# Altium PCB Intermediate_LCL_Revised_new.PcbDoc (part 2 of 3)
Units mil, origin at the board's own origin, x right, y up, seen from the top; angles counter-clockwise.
Board outline 12850 x 6950 mil, 4 copper layers (Top Layer, Lay1, gnd, Bottom Layer), stack 23.756 mil thick; 473 components, 243 nets, 1278 pads, 73 vias.
Unrouted connection lines stored in the file: 289.
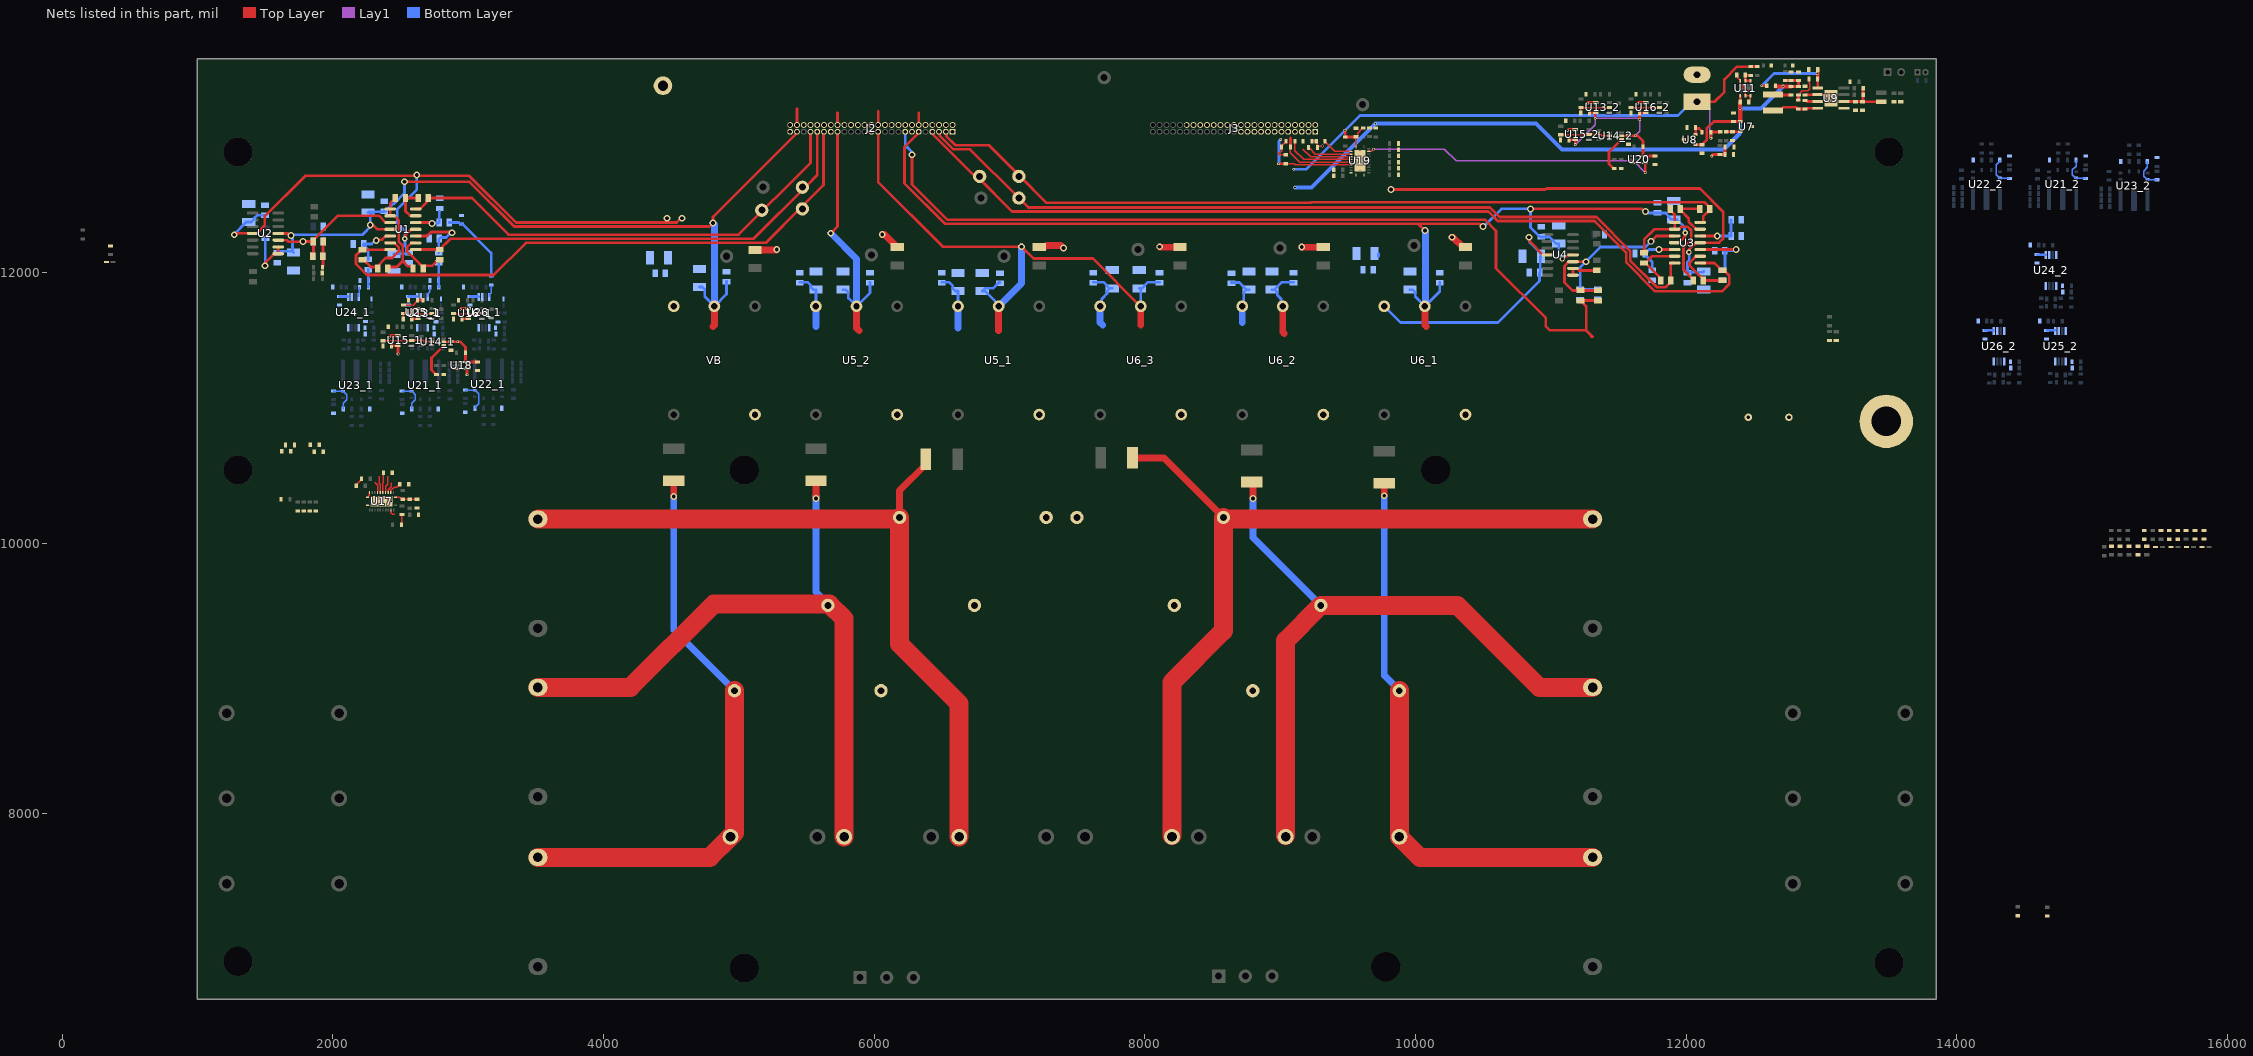
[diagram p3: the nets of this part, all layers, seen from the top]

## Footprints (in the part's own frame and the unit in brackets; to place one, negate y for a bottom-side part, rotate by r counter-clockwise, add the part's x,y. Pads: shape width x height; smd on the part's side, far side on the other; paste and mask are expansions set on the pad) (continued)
SHF-125-01-L-D-RA [mm] "50-Pin Simplus Connector"
  rect 1.09x1.09 hole 0.74 mask+0.381: 01(-15.24,-0.508)
  round 1.09 hole 0.74 mask+0.381: 02(-15.24,0.762) 03(-13.97,-0.508) 04(-13.97,0.762) 05(-12.7,-0.508) 06(-12.7,0.762) 07(-11.43,-0.508) 08(-11.43,0.762) 09(-10.16,-0.508) 10(-10.16,0.762) 11(-8.89,-0.508) 12(-8.89,0.762) 13(-7.62,-0.508) 14(-7.62,0.762) 15(-6.35,-0.508) 16(-6.35,0.762) 17(-5.08,-0.508) 18(-5.08,0.762) 19(-3.81,-0.508) 20(-3.81,0.762) 21(-2.54,-0.508) 22(-2.54,0.762) 23(-1.27,-0.508) 24(-1.27,0.762) 25(0,-0.508) 26(0,0.762) 27(1.27,-0.508) 28(1.27,0.762) 29(2.54,-0.508) 30(2.54,0.762) 31(3.81,-0.508) 32(3.81,0.762) 33(5.08,-0.508) 34(5.08,0.762) 35(6.35,-0.508) 36(6.35,0.762) 37(7.62,-0.508) 38(7.62,0.762) 39(8.89,-0.508) 40(8.89,0.762) 41(10.16,-0.508) 42(10.16,0.762) 43(11.43,-0.508) 44(11.43,0.762) 45(12.7,-0.508) 46(12.7,0.762) 47(13.97,-0.508) 48(13.97,0.762) 49(15.24,-0.508) 50(15.24,0.762)
  silkscreen extent -19.8,-0.61 19.05,7.36, body extent -19.05,-0.71 19.05,7.37, height 5.59
SOD-523_L1.2-W0.8-LS1.6-RD [mm]
  rect 0.93x0.36 smd: 1(-0.635,0) 2(0.635,0)
  silkscreen extent -0.91,-0.55 0.68,0.55
SOIC-14 [mm]
  oval 2.2x0.6 smd: 1(-2.4,3.81) 2(-2.4,2.54) 3(-2.4,1.27) 4(-2.4,0) 5(-2.4,-1.27) 6(-2.4,-2.54) 7(-2.4,-3.81) 8(2.4,-3.81) 9(2.4,-2.54) 10(2.4,-1.27) 11(2.4,0) 12(2.4,1.27) 13(2.4,2.54) 14(2.4,3.81)
  silkscreen extent -2.52,-4.4 0.9,4.78, body extent -2,-4.38 2,4.38, height 1.75
SOT-23-5_L3.0-W1.7-P0.95-LS2.8-BR [mm]
  rect 1x0.6 smd: 1(1.3,-0.95) 2(1.3,0) 3(1.3,0.95) 4(-1.3,0.95) 5(-1.3,-0.95)
  silkscreen extent -0.9,-1.78 1.65,1.55
VISH-TLMX1100_V [mm] "SMD, 2-Leads, Body 1.6x0.8mm"
  rect 0.6x0.8 smd: 1(-0.725,0) 2(0.725,0)
  silkscreen extent 1.53,-0.4 1.53,0.4, body extent -0.8,-0.4 0.8,0.4, height 0.65

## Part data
C1 C6 C11 C16: library part C2012X5R1H225K125AB, "SMD Multilayer Ceramic Capacitor, 2.2 µF, 50 V, 0805 [2012 Metric], ± 10%, X5R, C"
C2 C4 C7 C9 C12 C14 C17 C19 C23_1 C23_2 C23_3 C25_1 C25_2 C25_3 C28_1 C28_2 C28_3 C30_1 C30_2 C30_3: library part C0805C104J5RACTU, "SMD Multilayer Ceramic Capacitor, 0.1 µF, 50 V, 0805 [2012 Metric], ± 5%, X7R, C Series KEMET"
C3 C5 C8 C10 C13 C15 C18 C20 C24_1 C24_2 C24_3 C26_1 C26_2 C26_3 C29_1 C29_2 C29_3 C31_1 C31_2 C31_3: library part C3216X7R1H475K160AC, "SMD Multilayer Ceramic Capacitor, 4.7 µF, 50 V, 1206 [3216 Metric], ± 10%, X7R, C", Package=None
C21: library part 102_Y, "Y Earth Capacitor", Package=None
C22_1 C22_2 C22_3 C27_1 C27_2 C27_3: library part PHE450HF7220JR06L2, "KEMET PHE450 Metallised Polypropylene Film Capacitor, 180 V ac, 250 V dc, ±5%, 2.2μF, Through Hole", Manufacturer_Name=KEMET
C32 C33 C34 C35 C36 C37 C38 C39 C40 C41 C42 C43 C44 C45 C46 C47 C48 C50 C51 C54 C55_1 C55_2 C56_1 C56_2 C57_1 C57_2 C58_1 C58_2 C59_1 C59_2 C60_1 C60_2 C61_1 C61_2 C62 C63 C64 C65 C66 C67 C68 C69 C70 C71 C72 C73 C74 C75 C76 C77 C78 C79 C80 C81 C82 C83 C84_1 C84_2 C85_1 C85_2 C86_1 C86_2 C87_1 C87_2 C88_1 C88_2 C89_1 C89_2 C90_1 C90_2 C91_1 C91_2 C92_1 C92_2 C93_1 C93_2 C94_1 C94_2 C95_1 C95_2 C96_1 C96_2 C97_1 C97_2 C98_1 C98_2 C99_1 C99_2 C100_1 C100_2 C101_1 C101_2 C102_1 C102_2 C103_1 C103_2 C104_1 C104_2 C105_1 C105_2 C106_1 C106_2 C107_1 C107_2 C108_1 C108_2 C109_1 C109_2 C110_1 C110_2 C111_1 C111_2 C112_1 C112_2 C113_1 C113_2 C114_1 C114_2 C115_1 C115_2 C116_1 C116_2 C117_1 C117_2 C118_1 C118_2 C119_1 C119_2: library part Cap, "Capacitor"
C53: library part CE, "直插电解电容"
D1 D2 D3 D4 D5 D6 D7 D8: Average Rectified Current (Io)=70mA, Forward Voltage (Vf@If)=1V@15mA, JLCPCB Part Class="Extended Part", LCSC Part Name="电压:70V 电流:70mA", Manufacturer=Nexperia(安世), Reverse Leakage Current (Ir)=10uA@70V, Reverse Voltage (Vr)=70V
DS1 DS2: library part CMP-1666-00027-1_1, "LED, RED, 2.1 V, -40 to 100 degC, 2-Pin SMD (0603), RoHS, Tape and Reel", Capacitance="12 pF", Case Code (Imperial)=0603, Case Code (Metric)=1608, Max Operating Temperature=125degC, Min Operating Temperature=-55degC, Package Quantity=4000, Resistance="100000000000 Ohm", Tolerance=5%, Type (Capacitors)=C0G, Voltage Rating="50 V"
J2 J3: library part SHF-125-01-L-D-RA, "50-Pin Simplus Connector", Package=None
J4 J7: library part 3PinTerminal, "3 Position Terminal Block 5.08mm", Digikey Part Number=ED2610-ND, Manufacturer="On Shore Technology", Package=HDR03, Part Number=OSTTC032162, Temperature="-30°C to +105°C", Temperature Range High=+105°C, Temperature Range Low=-30°C, Voltage=300V
L1 L2: library part "30mH Custom CM Choke", "30mH Custom CM Choke", Manufacturer_Name="Wurth Elektronik", Manufacturer_Part_Number=744839029220, Mouser Part Number=710-744839029220
L3_1 L3_2 L3_3 L5_1 L5_2 L5_3: library part "4mH Custom Inductor"
L4_1 L4_2 L4_3 L6_1 L6_2 L6_3: library part "380uH Custom Inductor"
L7 L8: library part L-NR, "NR磁胶电感"
P1: "Header, 2-Pin"
R1 R3 R7 R9: library part CRCW080520K0FKEA, "SMD Chip Resistor, 20 kohm, ± 1%, 125 mW, 0805 [2012 Metric], Thick Film, General Purpose", Package="6432 Stackpole"
R2 R6 R8 R12 R17_1 R17_2 R17_3 R20_1 R20_2 R20_3 R21_1 R21_2 R21_3 R24_1 R24_2 R24_3: library part CRCW0805200KFKEA, "SMD Chip Resistor, 200 kohm, ± 1%, 125 mW, 0805 [2012 Metric], Thick Film, General Purpose", Package="6432 Stackpole"
R4 R5 R10 R11 R18_1 R18_2 R18_3 R19_1 R19_2 R19_3 R22_1 R22_2 R22_3 R23_1 R23_2 R23_3: library part CRCW080510K0FKEA, "SMD Chip Resistor, 10 kohm, ± 1%, 125 mW, 0805 [2012 Metric], Thick Film, General Purpose", Package="6432 Stackpole"
R13_1 R13_2 R13_3 R15_1 R15_2 R15_3: library part MCHP122WF1002T4E, "SMD Chip Resistor, 10 kohm, ± 1%, 2 W, 2512 [6432 Metric], Thick Film, High Power", Package="6432 Stackpole"
R14_1 R14_2 R14_3 R16_1 R16_2 R16_3: library part CRCW1206130RFKEA, "SMD Chip Resistor, 130 ohm, ± 1%, 250 mW, 1206 [3216 Metric], Thick Film, General Purpose", Package="6432 Stackpole"
R25 R26 R27 R28 R29 R30 R31 R32 R33 R34 R35 R36 R37 R38 R42 R43 R55 R56 R57_1 R57_2 R58_1 R58_2 R59_1 R59_2 R60_1 R60_2 R61_1 R61_2 R62_1 R62_2 R63_1 R63_2 R64_1 R64_2 R65_1 R65_2 R68 R69 R70 R71 R72 R73 R74 R75 R76 R77 R78 R79 R80 R81 R82 R83 R84 R85 R86 R87 R88 R89 R90 R91 R92 R93 R94 R95 R96 R97 R98 R99 R102 R103 R104 R105 R106 R107 R108 R109 R110 R111 R112 R113 R114 R115 R116 R117 R118 R119 R120 R121 R122 R123 R124_1 R124_2 R125_1 R125_2 R126_1 R126_2 R127_1 R127_2 R128_1 R128_2 R129_1 R129_2 R130_1 R130_2 R131_1 R131_2 R132_1 R132_2 R133_1 R133_2 R134_1 R134_2 R135_1 R135_2 R136_1 R136_2 R137_1 R137_2 R138_1 R138_2 R139_1 R139_2 R140_1 R140_2 R141_1 R141_2 R142_1 R142_2 R143_1 R143_2 R144_1 R144_2 R145_1 R145_2 R146_1 R146_2 R147_1 R147_2 R148_1 R148_2 R149_1 R149_2 R150_1 R150_2: library part "0603 100KΩ (1003) 1%_4", "贴片电阻", Package=0603, SuppliersPartNumber=C25803
R66 R67 R100 R101: library part Res, "Resistor 0402"
TP1 TP2 TP3 TP4 TP5 TP6 TP7 TP8 TP9 TP10 TP12 TP13 TP14 TP15 TP16 TP18: library part PCBTestpoint, "20-313143 PCB Test Point, White, Through Hole Mount, 1.32 mm, Phosphor Bronze, Tin Plated Contacts"
TP19: library part GroundTestPoint, "H2182-01 PCB Test Point, PCB Mount, 1.9 mm, Brass, Tin Plated Contacts"
U1 U2 U3 U4: library part TL074D, "Quad, 30-V, 3-MHz, high slew rate (13-V/µs), In to V+, JFET-input op amp"
U5_1 U5_2 U6_1 U6_2 U6_3 VB: "Undefined or Miscellaneous", Manufacturer_Name=LEM
U7 U8: library part CMP-0367-00146-2, "30 ppm / degC Drift, 3.9 uA Voltage Reference, -40 to 125 degC, 3-pin SOT-23 (DBZ), Green (RoHS & no Sb/Br)", Manufacturer="Texas Instruments", Rating=Catalog, Temp Coeff(Max)(ppm/ degree C)=30, Temp Coeff(Typ)(ppm/ degree C)=8
U9: library part LM5017MRXNOPB, "No Description Available", Mfr_Name="Texas Instruments"
U11: library part CMP-0062-01590-5, "IC REG LINEAR 3.3V 500MA 6WSON", Dropout Voltage=330mV, Max Input Voltage=10V, Max Operating Temperature=125°C, Max Output Current=500mA, Min Input Voltage=2.7V, Min Operating Temperature=-40°C, Nominal Output Voltage=3.3V, Output Voltage Accuracy=2%, Package Quantity=1000, Quiescent Current=100uA
U13_1 U13_2 U15_1 U15_2 U16_1 U16_2: Input Bias Current (Ib)=5nA, Input Hysteresis Voltage (Vhys)=1.2mV, Input Offset Voltage (Vos)=1mV, JLCPCB Part Class="Extended Part", Manufacturer=TI(德州仪器), Operating Temperature=-40℃~+125℃, Supply Current=40uA, Supply Voltage=2.7V~5.5V
U14_1 U14_2: library part CMP-0859-00464-4, "IC GATE OR 1CH 3-INP SC70-6", Ambient Temperature Range High=+125°C, Ambient Temperature Range Low=-40°C, Manufacturer="Texas Instruments", Max Supply Voltage=5.5V, Min Supply Voltage=1.65V, Nominal Supply Current=10uA, Package=DCK0006A, Temperature="-40°C to +125°C"
U17 U19: "No Description Available", Manufacturer="Texas Instruments", PartNumber=SN74AVC8T245RHL
U18 U20: library part CMP-0859-00376-4, "IC GATE OR 1CH 2-INP SC70-5", Case/Package=SC, High Level Output Current=-32mA, Low Level Output Current=32mA, Max Operating Temperature=125°C, Max Supply Voltage=5.5V, Min Operating Temperature=-40°C, Min Supply Voltage=1.65V, Package Quantity=1, Quiescent Current=10uA
U21_1 U21_2 U22_1 U22_2 U23_1 U23_2: library part CMP-04912-000022-2, "None", Case/Package=QFN, Max Operating Temperature=125°C, Min Operating Temperature=-40°C, Output Current per Channel=10A
U24_1 U24_2 U25_1 U25_2 U26_1 U26_2: "No Description Available", Mfr_Name="Texas Instruments"

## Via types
v1: diameter 50, hole 28, Top Layer to Bottom Layer, 40 vias
v2: diameter 20, hole 12, Top Layer to Bottom Layer, 29 vias
v3: diameter 40, hole 20, Top Layer to Bottom Layer, 4 vias

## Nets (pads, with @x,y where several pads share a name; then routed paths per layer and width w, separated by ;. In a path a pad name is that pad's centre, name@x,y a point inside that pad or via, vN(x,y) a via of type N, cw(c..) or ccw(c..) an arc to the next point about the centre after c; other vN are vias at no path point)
1.65A: R22_1.1 R22_2.1 R22_3.1 U1.1 U1.2 | length 780.3
  Top Layer w20: R22_1.1@2400,12040 2472.6,12040 2516.93,12084.33 ; R22_3.1@2462.6,12550 2462.6,12541.14 2452.52,12531.06 2444.02,12531.06 2423.62,12510.67 U1.1@2423.62,12468.86 U1.2@2423.62,12418.86 2455.12,12418.86 2486.93,12387.05 2486.93,12229.47 2516.93,12199.47 2516.93,12084.33 ; R22_2.1@2592.6,12030 2592.6,12034.97 2582.52,12045.05 2556.21,12045.05 2516.93,12084.33
1.65B: R18_1.1 R18_2.1 R18_3.1 U3.1 U3.2 | length 1086.5
  Top Layer w20: R18_1.1@11690,12144.8 11690,12243.64 11765.67,12319.31 11914.82,12319.31 U3.2@11915.51,12320 ; R18_3.1@11882.6,12470 11882.6,12461.14 11915.51,12428.23 U3.1@11915.51,12370 U3.2@11915.51,12320 ; R18_2.1@12052.6,11940 12052.6,11948.86 11981.18,12020.28 11981.18,12184.33 12038.46,12241.62 12038.46,12312.1 12012.1,12338.46 11966.45,12338.46 11947.99,12320 U3.2@11915.51,12320
1.65C: R4.1 U2.1 U2.2 | length 449.1
  Top Layer w20: v1(1500,12050) 1505.74,12055.74 1505.74,12079.01 1564.41,12137.68 1587.68,12137.68 1588.86,12138.86 1595.41,12138.86 1597.09,12140.53 U2.2@1597.09,12188.86 U2.1@1597.09,12138.86
  Bottom Layer w20: v1(1500,12050) 1501.3,12051.3 1501.3,12250.16 R4.1@1502.6,12251.46
1.65D: R10.1 U4.1 U4.2 | length 251.1
  Top Layer w20: U4.1@11135.74,11978.33 11162.82,11978.33 U4.1@11164.49,11980 U4.2@11164.49,12030 11196.96,12030 11211.77,12015.2 R10.1@11330,12015.2
3.3A: C1.2 R1.2 R77.2 | length 174.1
  Top Layer w20: R77.2@1923,12040 1923,12044.92 1927.4,12049.32 C1.2@1927.4,12120 ; C1.2@1924.49,12138.86 1927.24,12141.61 1927.24,12226.1 R1.2@1930,12228.86
3.3B: C11.2 J2.15 R7.2 R106.2 | length 6477.9
  Top Layer w20: v1(6280,12870) 6280,12650 6540,12390 10513.64,12390 10596.08,12307.56 10596.08,12029.96 10963.61,11662.44 10963.61,11645.87 10962.44,11644.7 10962.44,11605.3 10995.18,11572.56 11262.44,11572.56 ; R7.2@11220,11792.6 R7.2@11228.86,11792.6 ; 11300.5,11525 11310,11525 11262.44,11572.56 ; C11.2@11350,11792.6 R7.2@11228.86,11792.6 ; R7.2@11228.86,11792.6 11238.94,11782.52 11238.94,11773.66 11262.44,11750.16 11262.44,11572.56
  Bottom Layer w20: J2.15@6230,13040 6230,12940 6280,12890 v1(6280,12870)
3V3: C55_1.1 C55_2.1 C57_1.1 C57_2.1 C58_1.1 C58_2.1 C60_1.1 C60_2.1 C62.1 C72.1 C73.1 C83.1 C111_1.2 C111_2.2 C115_1.2 C115_2.2 C119_1.2 C119_2.2 D1.1 D2.1 D3.1 D4.1 D5.1 D6.1 D7.1 D8.1 J17.1 R25.2 R30.2 R42.2 R43.2 R66.2 R70.1 R92.1 R100.2 R105.1 R121.1 U13_1.5 U13_2.5 U14_1.5 U14_2.5 U15_1.5 U15_2.5 U16_1.5 U16_2.5 U17.1 U18.5 U19.1 U20.5 U24_1.5 U24_2.5 U25_1.5 U25_2.5 U26_1.5 U26_2.5 | length 7085.9
  Top Layer w10: U17.1@2464.33,10339.02 2495.88,10339.02 2511.04,10323.86 R70.1@2515.96,10323.86 2516.04,10323.78 2621.62,10323.78 C62.1@2621.71,10323.69 C62.1@2622.31,10323.09 ; v2@9101.25,12763.09 v2(9101.86,12762.48) ; C73.1@9559.71,13002.38 9566.6,13002.38 9573.41,13009.19 9573.41,13027.35 9593.41,13047.35 9593.41,13051.47 9610.32,13068.38 R100.2@9615.24,13068.38 ; C73.1@9560.2,12998.31 9560.2,12929.8 U19.1@9560.47,12929.53
  Top Layer w15: U14_1.5@2820.42,11487.72 C57_1.1@2871.23,11487.72 ; U14_2.5@11521.91,13009.93 C57_2.1@11572.72,13009.93
  Top Layer w20: C58_1.1@2434,11457.49 2435.3,11458.79 2478.84,11458.79 U15_1.5@2480.14,11460.09 2480.7,11460.09 2482.51,11458.28 v2(2482.51,11397.49) ; C55_1.1@2584,11657.49 2585.3,11658.79 2628.84,11658.79 U13_1.5@2630.14,11660.09 ; C57_1.1@2871.23,11487.72 2871.46,11487.49 v2(2922.51,11487.49) 2942.51,11487.49 2980,11450 R92.1@2980,11406.78 2980,11340.98 2981.81,11339.16 U18.5@2985.98,11339.16 C72.1@3070.24,11339.09 ; C60_1.1@2954,11657.49 2955.3,11658.79 2998.84,11658.79 U16_1.5@3000.14,11660.09 ; v2(9480,13050) 9481.25,13048.75 R105.1@9481.25,13001.24 C73.1@9557.26,13001.24 ; C58_2.1@11135.49,12979.71 11136.79,12981.01 11180.33,12981.01 U15_2.5@11181.32,12982 ; v2(11181.32,12945) U15_2.5@11181.32,12982 ; U15_2.5@11181.63,12982.31 U15_2.5@11181.32,12982 ; C55_2.1@11285.49,13179.71 11286.79,13181.01 U13_2.5@11329.84,13181.01 ; v2(11329.33,13138.74) 11329.33,13180.5 U13_2.5@11329.84,13181.01 ; U13_2.5@11331.63,13182.31 11330.33,13181.01 U13_2.5@11329.84,13181.01 ; C57_2.1@11572.72,13009.93 11572.95,13009.71 v2(11624,13009.71) 11644,13009.71 11681.49,12972.22 11681.49,12863.19 11683.3,12861.38 U20.5@11687.47,12861.38 ; v2(11657.41,13130.44) 11655.49,13132.36 C60_2.1@11655.49,13179.71 11656.79,13181.01 11700.33,13181.01 U16_2.5@11701.63,13182.31 ; U20.5@11687.51,12861.34 C83.1@11771.73,12861.31 ; J17.1@12041.18,13261.79 J17.1@12081.18,13261.79 12211.18,13261.79 12283.04,13333.65 12283.04,13426.84 12377.39,13521.2 R42.2@12477.05,13521.2 12477.24,13521.39 12527.26,13521.39 R43.2@12527.45,13521.58 ; v2(12183.72,12991.81) R30.2@12183.72,13037.79 12184.52,13038.59 12251.15,13038.59 R25.2@12251.95,13039.39
  Lay1 w10: v2(11181.32,12945) 11329.33,13093.01 v2(11329.33,13138.74) 11645.67,13138.74 11652.06,13132.35 11655.5,13132.35 v2(11657.41,13130.44) 11657.41,13043.13 v2(11624,13009.71) ; J17.1@12081.18,13261.79 12121.18,13261.79 12176.18,13206.79 12176.18,13002.06 12183.72,12994.52 v2(12183.72,12991.81)
  Bottom Layer w10: v2@9101.25,12763.09 v2(9101.86,12762.48)
  Bottom Layer w20: C111_1.2@2050,11822.99 2109.14,11822.99 U24_1.5@2111.2,11820.93 ; C115_1.2@2560,11822.99 U25_1.5@2618.21,11822.99 ; C119_1.2@3015.32,11822.99 3073.53,11822.99 U26_1.5@3076.53,11820 ; v2(9101.86,12762.48) 9192.48,12762.48 v2(9480,13050) 9590,13160 11655.49,13160 ; v2(11657.41,13130.44) 11655.49,13132.36 11655.49,13160 ; J17.1@12081.18,13261.79 12041.18,13261.79 11939.39,13160 11655.49,13160 ; C119_2.2@14209.55,11572.07 14267.76,11572.07 U26_2.5@14270.76,11569.07 ; C111_2.2@14594.23,12132.07 14653.37,12132.07 U24_2.5@14655.44,12130 ; C115_2.2@14664.23,11572.07 U25_2.5@14722.44,11572.07
3V3_LaunchPad_IN: J17.2
5V: C33.1 C35.2 C37.1 C39.1 C40.2 C41.2 C50.2 R29.2 R33.2 R67.2 R101.2 R124_1.2 R124_2.2 R127_1.2 R127_2.2 R130_1.2 R130_2.2 U7.1 U8.1 U11.1 | length 5141.6
  Top Layer w20: U8.1@12069.97,12944.83 12070.23,12944.58 12116.87,12944.58 C39.1@12117.13,12944.32 12124.02,12944.32 12125.83,12946.13 12125.83,12953.02 12151.91,12979.1 12151.91,13062.81 12205.24,13116.14 12344.36,13116.14 12345.32,13115.18 U7.1@12400.51,13115.17 U7.1@12400.75,13115.42 ; C50.2@12400,13260 12400.29,13260.29 12400.29,13306.39 U11.1@12400.57,13306.67 ; R29.2@12731.2,13419.15 12731.26,13419.09 12830.56,13419.09 C40.2@12830.62,13419.03 C37.1@12830.62,13374.68 C35.2@12776.68,13374.68
  Top Layer w30: v2(12398.88,13212.22) 12400.51,13210.59 U7.1@12400.51,13115.17 ; v2@12400,13212.22 C50.2@12400,13260 ; R33.2@12661.6,13374.68 C35.2@12776.68,13374.68
  Bottom Layer w30: v2(9110,12627.98) 9233.65,12627.98 9705.68,13100 10892.52,13100 11082.52,12910 12280,12910 12398.88,13028.88 v2(12398.88,13212.22) 12553.16,13212.22 v2(12716.29,13375.35)
  other v2: 9705.04,13099.36
+15V: C2.2 C3.2 C7.2 C8.2 C12.2 C13.2 C17.2 C18.2 C23_1.2 C23_2.2 C23_3.2 C24_1.2 C24_2.2 C24_3.2 C28_1.2 C28_2.2 C28_3.2 C29_1.2 C29_2.2 C29_3.2 J2.11 J2.23 J2.35 J2.47 U1.4 U2.4 U3.4 U4.4 U5_1.3 U5_2.3 U6_1.3 U6_2.3 U6_3.3 VB.3 | length 21227.2
  Top Layer w20: U2.4@1597.09,12288.86 1597.78,12288.17 1666.45,12288.17 ; v1@2298.12,12350 2329.26,12318.86 U1.4@2423.62,12318.86 ; v1(2530,12670) 3010,12670 3340.79,12339.21 4783.28,12339.21 4809.07,12365 v1(4810,12365) 4810,12411.37 5421.46,13022.83 5421.46,13025.26 5430,13033.8 J2.47@5430,13040 ; v1(5680,12290) 5730,12340 J2.35@5730,13040 ; J2.23@6030,13040 6030,12667.57 6507.57,12190 v1(7090,12190) 7177.4,12102.6 7617.4,12102.6 U6_3.3@7970,11750 ; J2.11@6330,13040 6321.46,13040 6321.46,13022.83 6225,12926.37 6225,12657.43 6522.43,12360 10020,12360 ; v1(10070,12310) 10020,12360 ; v1(10500,12340) 10493.28,12340 10473.28,12360 10020,12360 ; v1(10850,12470) 11671.88,12470 11691.88,12450 v1(11700,12450) ; v3(11085,12100) 11093.12,12100 11108.88,12115.76 11117.77,12115.76 11132.01,12130 U4.4@11164.49,12130 ; U3.4@11915.51,12220 11916.69,12221.18 11948.19,12221.18 11991.61,12264.6 11991.61,12291.61 v3(11993.46,12293.46)
  Top Layer w50: 4810,11600 4820,11610 VB.3@4820,11750 ; U5_2.3@5870,11750 5870,11590 5890,11570 ; 6920,11570 U5_1.3@6920,11750 ; 7970,11610 U6_3.3@7970,11750 ; U6_2.3@9020,11750 9020,11560 9030,11550 ; U6_1.3@10070,11750 10070,11610 10080,11600
  Bottom Layer w20: C7.2@1590,12157.4 1699.53,12157.4 C8.2@1710,12146.93 ; C8.2@1698.41,12161.59 1702.6,12165.79 1702.6,12260.14 v1(1690.36,12272.38) 1695.77,12277.8 2217.8,12277.8 v1@2290,12350 ; C3.2@2260,12443.07 2264.76,12447.83 2375.24,12447.83 C2.2@2380,12452.6 2388.86,12452.6 2443.23,12506.97 2450.71,12506.97 2530,12586.26 v1(2530,12670) ; v1(2277.4,12351.14) C3.2@2277.4,12435.67 ; C3.2@2282.6,12441.93 C3.2@2302.28,12441.93 ; C24_3.2@4710,11893.07 4729.69,11893.07 4749.21,11873.54 4749.21,11820.79 VB.3@4820,11750 4910,11840 C23_3.2@4910,11936.22 ; C24_2.2@5770,11873.07 5789.69,11873.07 5809.21,11853.54 5809.21,11810.79 U5_2.3@5870,11750 5970,11850 C23_2.2@5970,11928.11 ; U5_1.3@6920,11750 6920,11762.76 6819.69,11863.07 C24_1.2@6800,11863.07 6819.53,11882.6 6877.52,11882.6 6921.14,11926.22 C23_1.2@6930,11926.22 ; U6_3.3@7970,11750 7970,11873.07 C29_3.2@7960,11883.07 7979.69,11883.07 8024.72,11928.11 C28_3.2@8110,11928.11 ; C29_2.2@8940,11873.07 C29_2.2@8959.68,11873.07 ; U6_2.3@9020,11750 9007.25,11762.75 9007.25,11805.82 8979.21,11833.86 8979.21,11853.54 C29_2.2@8959.68,11873.07 ; C28_2.2@9100,11928.11 9014.72,11928.11 C29_2.2@8959.68,11873.07 ; C29_1.2@9960,11873.07 9979.68,11873.07 9999.21,11853.54 9999.21,11820.79 U6_1.3@10070,11750 10074.21,11754.21 10180,11860 C28_1.2@10180,11928.11 ; v1(10500,12340) 10505,12340 10635,12470 v1(10850,12470) 10850,12333.74 10921.14,12262.6 10990.79,12262.6 11040.32,12213.07 C18.2@11060,12213.07 11060,12133.12 11085,12108.12 v3(11085,12100) ; v1(11700,12450) 11708.12,12450 11718.12,12440 C12.2@11790,12440 11848.94,12440 11870.79,12418.15 11870.79,12412.6 11890.32,12393.07 C13.2@11910,12393.07 11929.68,12393.07 11987.72,12335.03 11987.72,12299.2 v3(11993.46,12293.46)
  Bottom Layer w50: v1(4810,12365) 4820,12355 VB.3@4820,11750 ; v1(5680,12290) 5870,12100 U5_2.3@5870,11750 ; U5_1.3@6920,11750 7090,11920 v1(7090,12190) ; v1(10070,12310) 10074.21,12305.79 U6_1.3@10074.21,11754.21
-15V: C4.2 C5.2 C9.2 C10.2 C14.2 C15.2 C19.2 C20.2 C25_1.2 C25_2.2 C25_3.2 C26_1.2 C26_2.2 C26_3.2 C30_1.2 C30_2.2 C30_3.2 C31_1.2 C31_2.2 C31_3.2 J2.12 J2.24 J2.36 J2.48 U1.11 U2.11 U3.11 U4.11 U5_1.4 U5_2.4 U6_1.4 U6_2.4 U6_3.4 VB.4 | length 12302.5
  Top Layer w20: v1(1272.6,12278.86) 1280.72,12278.86 1290.72,12288.86 U2.11@1408.11,12288.86 1439.61,12288.86 1496.36,12345.61 1496.36,12414.61 1796.74,12715 3007.43,12715 3353.21,12369.21 4541.09,12369.21 4571.88,12400 v1(4580,12400) ; v3(2531.93,12250) 2537.67,12255.74 2537.67,12275.43 2579.92,12317.68 2611.42,12317.68 U1.11@2612.6,12318.86 ; J2.48@5430,13090 5430,13210 ; J2.36@5730,13090 5730,13180 ; J2.24@6030,13090 6030,13190 ; J2.12@6330,13090 6330,13180 ; v1(9820,12612.98) 10961.6,12612.98 10968.62,12620 12102.1,12620 12275,12447.1 12275,12251.36 12243.64,12220 U3.11@12104.49,12220 12103.31,12218.82 12071.81,12218.82 12025.01,12172.02 12025.01,12153.83 v3(12021.18,12150) ; v1(10840,12260) 10845.74,12254.26 10845.74,12228.28 10944.02,12130 U4.11@10975.51,12130 11006.03,12130 11007.7,12131.67 U4.11@11007.7,12135.71
  Top Layer w50: U6_2.4@8720,11750 U6_2.4@8720.43,11749.57
  Bottom Layer w20: v1(1272.6,12278.86) 1272.6,12285.35 1360.32,12373.07 C10.2@1380,12373.07 1399.68,12373.07 1419.21,12392.6 1419.21,12400.75 1441.06,12422.6 C9.2@1500,12422.6 ; C5.2@2452.6,12135.79 2455.08,12138.27 2560.12,12138.27 2562.6,12140.75 2553.74,12140.75 2543.66,12150.83 2543.66,12168.05 2543.66,12185 2533.66,12195 2533.66,12248.27 v3(2531.93,12250) 2531.93,12308.33 2475.52,12364.74 2475.52,12466.07 2620,12610.55 v1(2620,12720) ; C25_2.2@5450,11928.11 5508.94,11928.11 5530.79,11906.26 5530.79,11892.6 5550.31,11873.07 C26_2.2@5570,11873.07 U5_2.4@5570,11750 ; C25_1.2@6500,11928.11 6554.96,11928.11 6580.79,11902.28 6580.79,11882.6 6600.31,11863.07 C26_1.2@6620,11863.07 U5_1.4@6620,11750 ; C30_3.2@7620,11928.11 7695.28,11928.11 C31_3.2@7740.31,11883.07 ; U6_3.4@7670,11750 7682.75,11762.75 7682.75,11805.82 7720.79,11843.86 7720.79,11863.54 C31_3.2@7740.31,11883.07 ; C31_3.2@7760,11883.07 C31_3.2@7740.31,11883.07 ; C30_2.2@8640,11926.22 8698.94,11926.22 8730.79,11894.37 8730.79,11892.6 C31_2.2@8750.32,11873.07 ; U6_2.4@8720,11750 8730.79,11760.79 8730.79,11853.54 C31_2.2@8750.32,11873.07 ; C31_2.2@8770,11873.07 C31_2.2@8750.32,11873.07 ; 9726.93,12120.32 9726.93,12140 ; U6_1.4@9770,11750 9890,11630 10610,11630 10917.4,11937.4 C19.2@10917.4,12000 10922.17,12004.76 10922.17,12115.24 C20.2@10926.93,12120 10926.93,12139.68 10845.74,12220.87 10845.74,12254.26 v1(10840,12260) ; v3@12015.59,12155.59 12022.58,12148.6 12022.58,12090 12010,12077.42 C14.2@12010,11997.4 12014.76,12002.17 12125.24,12002.17 C15.2@12130,12006.93 ; v3(12021.18,12150) v3@12021.18,12155.41
  Bottom Layer w50: 5570,11600 U5_2.4@5570,11750 ; 6620,11590 U5_1.4@6620,11750 ; U6_3.4@7670,11750 7670,11630 7690,11610 ; 8720,11630 U6_2.4@8720,11750
  other v1: 4470,12400
C1_Neut: C22_1.1 C22_2.1 C22_3.1 U5_1.1 U5_2.1 VB.1
C2_Neut: C27_1.1 C27_2.1 C27_3.1 U6_1.1 U6_2.1 U6_3.1
CompRef: C34.1 R27.1 R28.2 U13_1.4 U13_2.4 U15_1.4 U15_2.4 U16_1.4 U16_2.4 | length 525.3
  Top Layer w20: v2(2416.76,11521.75) 2429,11533.99 2479.23,11533.99 U15_1.4@2480.14,11534.89 ; v2(2581.75,11721.75) 2593.08,11733.08 2628.33,11733.08 U13_1.4@2630.14,11734.89 ; v2(2942.51,11727.49) 2949,11733.99 2999.23,11733.99 U16_1.4@3000.14,11734.89 ; v2(11124,13049.71) 11130.49,13056.21 11180.72,13056.21 U15_2.4@11181.63,13057.11 ; v2(11272.19,13250.61) 11277.79,13256.21 11330.72,13256.21 U13_2.4@11331.63,13257.11 ; v2(11644,13249.71) 11650.49,13256.21 11700.72,13256.21 U16_2.4@11701.63,13257.11 ; v2(12190,12860) 12201.25,12871.25 R27.1@12250.7,12871.25 12251.01,12871.55 12287.78,12871.55 C34.1@12288.09,12871.86 R28.2@12288.09,12927.29
Earth: C21.2 J6.1
EPWM1A: J3.01 R118.2 U19.3 | length 248.8
  Top Layer w10: 9318.27,12981.73 9326.19,12981.73 9333,12974.92 R118.2@9333,12970 9333,12965.08 9403.98,12894.09 U19.3@9525.04,12894.09
EPWM1B: J3.03 R117.2 U19.4 | length 346.7
  Top Layer w10: R117.2@9208.23,12931.08 9206.45,12929.3 9206.45,12924.38 9213.26,12917.57 9218.18,12917.57 9261.34,12874.41 U19.4@9525.04,12874.41
EPWM2A: J3.05 R116.1 U19.5 | length 379.9
  Top Layer w10: 9168.97,12911.03 9225.86,12854.14 9371.75,12854.14 9372.33,12854.72 U19.5@9525.04,12854.72
EPWM2B: J3.07 R115.2 U19.6 | length 512.9
  Top Layer w10: R115.2@9109.57,12969.83 R115.2@9109.15,12969.4 9109.15,12900.85 9174.96,12835.04 U19.6@9525.04,12835.04 ; J3.07@9109.57,13039.57 J3.07@9110,13040
EPWM3A: J3.09 R114.2 U19.7 | length 585.6
  Top Layer w10: R114.2@9076.93,12927.35 9076.93,12883.07 9144.65,12815.35 U19.7@9525.04,12815.35
  Top Layer w20: R114.2@9076.96,12928.97 9076.96,12994.14
EPWM3B: J3.11 R113.2 U19.8 | length 734.2
  Top Layer w10: R113.2@9037.83,12803.76 9105.54,12803.76 9113.62,12795.67 U19.8@9525.04,12795.67
  Top Layer w20: v2(8988.82,12803.3) 8989.27,12803.76 R113.2@9037.83,12803.76
  Bottom Layer w20: v2(8988.82,12803.3) 8991.51,12805.99 8991.51,12970.48 v2(9004.38,12983.35) ; J3.11@9004.38,13034.38 J3.11@9010,13040
EPWM4A: J3.13 R89.2 U17.3 | length 109.1
  Top Layer w10: U17.3@2428.9,10374.45 2429.17,10374.72 2429.17,10389.17 2452.94,10412.94 2471.68,10412.94 2482.88,10424.14 2487.8,10424.14 2494.61,10430.95 R89.2@2494.61,10435.87 R89.2@2494.61,10440.79 ; J3.13@8958.82,13038.82 J3.13@8960,13040
EPWM4B: J3.15 R88.2 U17.4 | length 90.5
  Top Layer w10: U17.4@2409.21,10374.45 2409.21,10394.72 2431.9,10417.4 2431.9,10444.82 2432.08,10445 ; J3.15@8908.87,13038.87 J3.15@8910,13040
  Bottom Layer w10: J3.15@8910,13031.09 J3.15@8910,13040
EPWM5A: J3.17 R87.1 U17.5 | length 133
  Top Layer w10: U17.5@2389.53,10374.45 2389.53,10419.53 2404.9,10434.9 2404.9,10495
  Top Layer w20: J3.17@8860,13040 J3.17@8862.91,13037.09
  Bottom Layer w10: J3.17@8860,13040 J3.17@8861.41,13038.59
EPWM5B: J3.19 R86.2 U17.6 | length 155.6
  Top Layer w10: U17.6@2369.84,10374.45 2370.12,10374.72 2370.12,10445.09 2371.93,10446.9 2373.84,10448.81 R86.2@2373.84,10519.77 ; R86.2@2373.92,10519.77 R86.2@2380,10525.85
EPWM6A: J3.21 R85.2 U17.7 | length 133
  Top Layer w10: 2342.23,10495 2342.23,10444.56 2341.86,10444.19 2350.16,10435.89 U17.7@2350.16,10374.45
  Top Layer w20: J3.21@8760,13040 J3.21@8761.91,13038.09
  Bottom Layer w20: J3.21@8755.62,13035.62 J3.21@8760,13040
EPWM6B: J3.23 R84.2 U17.8 | length 84.4
  Top Layer w10: 2311.79,10445 2313.68,10445 2330.47,10428.21 U17.8@2330.47,10374.45
  Bottom Layer w10: J3.23@8710,13040 J3.23@8713.51,13036.49
GND: C2.1 C3.1 C4.1 C5.1 C6.1 C7.1 C8.1 C9.1 C10.1 C12.1 C13.1 C14.1 C15.1 C16.1 C17.1 C18.1 C19.1 C20.1 C21.1 C23_1.1 C23_2.1 C23_3.1 C24_1.1 C24_2.1 C24_3.1 C25_1.1 C25_2.1 C25_3.1 C26_1.1 C26_2.1 C26_3.1 C28_1.1 C28_2.1 C28_3.1 C29_1.1 C29_2.1 C29_3.1 C30_1.1 C30_2.1 C30_3.1 C31_1.1 C31_2.1 C31_3.1 C32.2 C33.2 C34.2 C38.2 C39.2 C40.1 C41.1 C43.2 C44.2 C45.2 C46.2 C47.1 C48.1 C50.1 C51.1 C55_1.2 C55_2.2 C56_1.2 C56_2.2 C57_1.2 C57_2.2 C58_1.2 C58_2.2 C59_1.2 C59_2.2 C60_1.2 C60_2.2 C61_1.2 C61_2.2 C62.2 C63.2 C64.2 C65.2 C66.2 C67.2 C68.2 C69.2 C70.2 C71.2 C72.2 C73.2 C74.2 C75.2 C76.2 C77.2 C78.2 C79.2 C80.2 C81.2 C82.2 C83.2 C88_1.1 C88_2.1 C90_1.2 C90_2.2 C91_1.2 C91_2.2 C96_1.1 C96_2.1 C98_1.2 C98_2.2 C99_1.2 C99_2.2 C104_1.1 C104_2.1 C106_1.2 C106_2.2 C107_1.2 C107_2.2 C108_1.2 C108_2.2 C110_1.2 C110_2.2 C111_1.1 C111_2.1 C112_1.2 C112_2.2 C114_1.2 C114_2.2 C115_1.1 C115_2.1 C116_1.2 C116_2.2 C118_1.2 C118_2.2 C119_1.1 C119_2.1 DS1.2 DS2.2 J2.01 J2.02 J2.04 J2.06 J2.08 J2.10 J2.13 J2.14 J2.16 J2.18 J2.20 J2.22 J2.25 J2.26 J2.28 J2.30 J2.32 J2.34 J2.37 J2.38 J2.40 J2.42 J2.44 J2.46 J2.49 J2.50 J3.02 J3.04 J3.06 J3.08 J3.10 J3.12 J3.14 J3.16 J3.18 J3.20 J3.22 J3.24 J3.26 J3.28 J3.30 J3.32 J3.34 J3.36 J3.38 J3.40 R3.1 R6.2 R9.1 R12.2 R14_1.1 R14_2.1 R14_3.1 R16_1.1 R16_2.1 R16_3.1 R20_1.1 R20_2.1 R20_3.1 R24_1.1 R24_2.1 R24_3.1 R28.1 R35.1 R37.1 R38.1 R55.1 R56.1 R78.2 R79.2 R80.2 R81.2 R82.2 R83.2 R84.1 R85.1 R86.1 R87.2 R88.1 R89.1 R90.2 R91.2 R94.1 R107.2 R108.2 R109.2 R110.2 R111.2 R112.2 R113.1 R114.1 R115.1 R116.2 R117.1 R118.1 R119.2 R120.2 R123.1 R137_1.1 R137_2.1 R143_1.1 R143_2.1 R149_1.1 R149_2.1 TP19.1 U7.3 U8.3 U9.1 U9.9 U11.2 U11.3 U11.6 U13_1.2 U13_2.2 U14_1.2 U14_2.2 U15_1.2 U15_2.2 U16_1.2 U16_2.2 U17.11 U17.12 U17.13 U17.25 U18.3 U19.11 U19.12 U19.13 U19.25 U20.3 U21_1.7 U21_2.7 U22_1.7 U22_2.7 U23_1.7 U23_2.7 U24_1.1 U24_1.4 U24_1.6 U24_2.1 U24_2.4 U24_2.6 U25_1.1 U25_1.4 U25_1.6 U25_2.1 U25_2.4 U25_2.6 U26_1.1 U26_1.4 U26_1.6 U26_2.1 U26_2.4 U26_2.6 | length 4742.9
  Top Layer w10: R91.2@2173.97,10425.73 2180.78,10432.54 2180.78,10439.68 2211.26,10470.16 R90.2@2211.26,10475.08 ; U17.12@2255.67,10339.02 2262.2,10339.02 2262.48,10339.29 2262.48,10345.83 2271.1,10354.45 U17.11@2271.1,10374.45 ; C59_1.2@2372.51,11496 2373.25,11496.75 2581.76,11496.75 U15_1.2@2582.51,11497.49 2666.94,11497.49 2676.72,11487.72 U14_1.2@2733.81,11487.72 ; R78.2@2504.7,10134.8 2504.7,10139.73 2508.96,10143.99 2508.96,10174.01 2510.88,10175.92 2510.88,10210.68 C63.2@2511.81,10211.62 ; C55_1.2@2521.01,11657.49 2521.01,11694.5 C56_1.2@2522.51,11696 2523.25,11696.75 2731.76,11696.75 U13_1.2@2732.51,11697.49 ; C61_1.2@2892.51,11696 2893.25,11696.75 3101.76,11696.75 U16_1.2@3102.51,11697.49 ; R113.1@9035.08,12873 R113.1@9040,12873 ; R113.1@9042.71,12870.18 9035.08,12870.18 8996.3,12870.18 8990.61,12875.87 8990.61,12880.79 8997.42,12887.61 9002.34,12887.61 9010.93,12896.19 R114.1@9010.93,12927.35 9010.93,12932.27 9017.74,12939.08 9043.15,12964.48 R115.1@9043.15,12969.4 ; R116.2@9235.78,12970.05 9266.95,12970.05 R118.1@9267,12970 9267,12965.08 9276.06,12956.02 R117.1@9276.06,12923.47 9276.06,12926.92 9282.87,12933.73 9311.78,12933.73 v2(9313.05,12935) ; C59_2.2@11074,13018.21 11074.74,13018.96 11283.25,13018.96 U15_2.2@11284,13019.71 11368.43,13019.71 11378.21,13009.93 U14_2.2@11435.3,13009.93 ; C55_2.2@11222.5,13179.71 11222.5,13216.72 C56_2.2@11224,13218.21 11224.74,13218.96 11433.25,13218.96 U13_2.2@11434,13219.71 ; C61_2.2@11594,13218.21 11594.74,13218.96 11803.25,13218.96 U16_2.2@11804,13219.71 ; C51.1@12375,13460 12381.81,13453.19 12381.81,13440.6 12400.57,13421.83 U11.6@12400.57,13416.91 12401.64,13415.85 12401.64,13388.29 12428.13,13361.79 12437.98,13361.79 U11.2@12437.98,13306.67 U11.3@12475.38,13306.67 12475.38,13279.28 12462.99,13266.89 C50.1@12462.99,13260
  Top Layer w50: R14_3.1@5120,12166.93 5276.93,12166.93 v1(5280,12170) ; v1(6060,12280) 6076.93,12280 R14_2.1@6170,12186.93 ; R14_1.1@7220,12186.93 7224.53,12191.46 7264.75,12191.46 7273.5,12200.21 7379.79,12200.21 v1(7400,12180) ; v1(8110,12190) 8113.07,12186.93 R16_3.1@8260,12186.93 ; v1(9159.39,12187.74) 9160.2,12186.93 R16_2.1@9320,12186.93 ; v1(10270,12260) 10277.24,12260 10350.32,12186.93 R16_1.1@10370,12186.93
  Bottom Layer w10: C104_1.1@2005.15,11124.74 2006.26,11123.63 2073.66,11123.63 U23_1.7@2074.76,11122.53 2078.7,11122.53 2103.54,11097.69 2103.54,11060.37 2076.69,11033.52 C107_1.2@2076.69,10990 ; C88_1.1@2513.16,11123.63 2580.56,11123.63 U21_1.7@2581.67,11122.53 2585.6,11122.53 2610.45,11097.69 2610.45,11060.37 2583.6,11033.52 C91_1.2@2583.6,10990 ; 2952.06,11114.74 2953.16,11113.63 ; C96_1.1@2980,11131.42 2981.1,11130.32 3052.44,11130.32 3078.39,11104.37 3078.39,11030.42 3051.54,11003.57 C99_1.2@3051.54,10996.68 ; C99_2.2@14318.46,12830.24 14318.46,12823.35 14291.61,12796.5 14291.61,12722.55 14317.56,12696.61 14388.9,12696.61 C96_2.1@14390,12695.5 ; C91_2.2@14881.56,12830.24 14881.56,12786.72 14854.71,12759.87 14854.71,12722.55 14879.55,12697.71 U21_2.7@14883.49,12697.71 14884.59,12696.61 14951.99,12696.61 C88_2.1@14953.09,12695.5 ; C107_2.2@15408.46,12820.24 15408.46,12776.72 15381.61,12749.87 15381.61,12712.55 15406.46,12687.71 U23_2.7@15410.39,12687.71 15411.5,12686.61 15478.9,12686.61 C104_2.1@15480,12685.5
  Bottom Layer w20: J3.40@8305.62,13094.38 J3.40@8310,13090
I_InA_1: C67.1 R23_1.1 R73.2 | length 131.6
  Bottom Layer w20: R23_1.1@2262.6,12021.46 2262.8,12021.26 2262.8,11890.2 R73.2@2263,11890
I_InA_2: C71.1 R23_2.1 R74.2 | length 181.6
  Bottom Layer w20: R23_2.1@2782.6,12071.46 2782.8,12071.26 2782.8,11890.2 R74.2@2783,11890
I_InA_3: C68.1 R23_3.1 R75.2 | length 575
  Bottom Layer w20: R23_3.1@2860,12368.86 2932.76,12368.86 2943.11,12358.5 C68.1@2950,12358.5 2956.89,12358.5 3170,12145.39 R75.2@3170,11973
I_InB_1: C78.1 R19_1.1 R99.2
I_InB_2: C82.1 R19_2.1 R102.2
I_InB_3: C79.1 R19_3.1 R103.2
I_NegA_1: R21_1.1 R22_1.2 U1.6 | length 485.2
  Top Layer w20: R21_1.1@2220,12092.6 2228.86,12092.6 2281.46,12040 R22_1.2@2325.2,12040 ; R22_1.2@2325.2,12041.46 2391.05,12107.31 2438.56,12107.31 2486.93,12155.68 2486.93,12187.05 2455.12,12218.86 U1.6@2423.62,12218.86 U1.6@2391.15,12218.86 ; R22_1.2@2332.6,12021.14 R22_1.2@2332.6,12030
I_NegA_2: R21_2.1 R22_2.2 U1.9 | length 424.7
  Top Layer w20: U1.9@2612.7,12218.75 U1.9@2612.6,12218.86 2581.1,12218.86 2549.29,12187.05 2549.29,12155.68 2602.66,12102.31 2603.95,12102.31 2667.4,12038.86 R22_2.2@2667.4,12030 ; R22_2.2@2667.4,12050 2735.95,12050 2781.14,12095.2 R21_2.1@2790,12095.2
I_NegA_3: R21_3.1 R22_3.2 U1.13 | length 261.8
  Top Layer w20: U1.13@2612.6,12418.86 2611.91,12419.55 2570.45,12419.55 2537.4,12452.6 R22_3.2@2537.4,12550 R21_3.1@2612.6,12550
I_NegB_1: R17_1.1 R18_1.2 U3.6 | length 423.3
  Top Layer w20: R18_1.2@11690,12070 R18_1.2@11698.86,12070 ; R17_1.1@11812.6,11940 11802.52,11950.08 11802.52,11966.34 R18_1.2@11698.86,12070 ; U3.6@11915.51,12120 11748.86,12120 R18_1.2@11698.86,12070
I_NegB_2: R17_2.1 R18_2.2 U3.9 | length 417
  Top Layer w20: U3.9@12104.49,12120 12073.64,12120 12025.11,12071.47 12025.11,12051.15 12127.4,11948.86 R18_2.2@12127.4,11940 12128.7,11941.3 12268.7,11941.3 R17_2.1@12270,11942.6
I_NegB_3: R17_3.1 R18_3.2 U3.13 | length 377.2
  Top Layer w20: R17_3.1@12103.7,12466.3 R17_3.1@12100,12470 R18_3.2@11957.4,12470 11957.4,12461.14 12019.89,12398.65 12019.89,12373.1 12072.99,12320 U3.13@12104.49,12320
I_OutA_1: J2.39 R21_1.2 TP13.1 U1.7 | length 4525.8
  Top Layer w20: U1.7@2391.15,12168.86 U1.7@2423.62,12168.86 2422.93,12168.17 2391.15,12168.17 2220.76,12168.17 R21_1.2@2220,12167.4 2211.14,12167.4 2171.06,12127.32 2171.06,12064.24 2254.24,11981.06 3188.64,11981.06 3426.79,12219.21 5199.21,12219.21 5465,12485 5625.62,12645.62 5625.62,13035.62 J2.39@5630,13040
I_OutA_2: J2.41 R21_2.2 TP14.1 U1.8 | length 3515.5
  Top Layer w20: U1.8@2612.6,12168.86 U1.8@2645.07,12168.86 ; U1.8@2645.07,12169.43 2789.43,12169.43 R21_2.2@2790,12170 2869.21,12249.21 5109.21,12249.21 5500,12640 5580,12720 J2.41@5580,13040
I_OutA_3: J2.43 R21_3.2 TP15.1 U1.14 | length 3525
  Top Layer w20: U1.14@2612.6,12468.86 2644.09,12468.86 2694.72,12519.49 2694.72,12539.92 R21_3.2@2704.8,12550 3027.57,12550 3298.36,12279.21 4999.21,12279.21 5530,12810 J2.43@5530,13040
I_OutB_1: J2.05 R17_1.2 TP2.1 U3.7 | length 6121.1
  Top Layer w20: J2.05@6480,13040 6484.38,13035.62 6484.38,13013.19 6587.57,12910 6710,12910 TP2.1@7070,12550 7140,12480 10550.92,12480 10620.92,12410 11337.13,12410 11586.94,12160.19 11586.94,12088.36 11784.24,11891.06 11847.32,11891.06 11887.4,11931.14 11887.4,12068.33 11889.07,12070 U3.7@11915.51,12070
I_OutB_2: J2.07 R17_2.2 TP3.1 U3.8 | length 6771.9
  Top Layer w20: J2.07@6430,13040 6434.38,13035.62 6434.38,13020.76 6730.14,12725.01 6754.99,12725.01 6770,12710 TP3.1@6780,12710 ; TP3.1@6770,12700 7020,12450 10538.49,12450 10608.49,12380 11324.7,12380 11556.94,12147.76 11556.94,12075.93 11771.81,11861.06 12265.76,11861.06 12318.94,11914.24 12318.94,11977.32 12278.86,12017.4 R17_2.2@12270,12017.4 12261.14,12017.4 12208.54,12070 U3.8@12104.49,12070
I_OutB_3: J2.03 R17_3.2 TP1.1 U3.14 | length 6047.7
  Top Layer w20: J2.03@6530,13040 6534.38,13035.62 6534.38,13005.62 6600,12940 6850,12940 7075,12715 7275,12515 9227.65,12515 9231.59,12518.94 12134.72,12518.94 12174.8,12478.86 12174.8,12461.14 12125.98,12412.32 12125.98,12371.67 12124.31,12370 U3.14@12104.49,12370
I_PosA_1: R23_1.2 R24_1.2 U1.5 | length 358.9
  Top Layer w20: v1(2321.48,12236.38) 2327.22,12242.12 2364.41,12242.12 2391.15,12268.86 U1.5@2423.62,12268.86
  Bottom Layer w20: R23_1.2@2261.3,12097.56 R23_1.2@2262.6,12096.26 2262.6,12165.94 2227.4,12201.14 R24_1.2@2227.4,12210 2286.99,12210 2313.37,12236.38 v1(2321.48,12236.38) v1@2315.74,12230.64
I_PosA_2: R23_2.2 R24_2.2 U1.10 | length 497.7
  Top Layer w20: U1.10@2612.6,12268.86 2696.96,12268.86 2726.96,12298.86 2875.35,12298.86 v1(2880,12294.21)
  Bottom Layer w20: R23_2.2@2782.6,12146.26 2783.9,12147.56 2783.9,12245.35 2797.4,12258.86 2837.57,12258.86 2872.93,12294.21 v1(2880,12294.21)
I_PosA_3: R23_3.2 R24_3.2 U1.12 | length 264.5
  Top Layer w20: U1.12@2612.6,12368.86 2716.75,12368.86 2724.21,12361.4 v1(2732.33,12361.4)
  Bottom Layer w20: v1(2732.33,12361.4) 2736.06,12365.13 2781.47,12365.13 R23_3.2@2785.2,12368.86 2787.6,12371.26 2787.6,12450.2 R24_3.2@2790,12452.6
I_PosB_1: R19_1.2 R20_1.2 U3.5 | length 380.1
  Top Layer w20: v1(11800,12170) U3.5@11915.51,12170
  Bottom Layer w20: R19_1.2@11750,12017.4 11750,12078.54 11697.4,12131.14 R20_1.2@11697.4,12140 11697.4,12148.86 11707.48,12158.94 11716.34,12158.94 11727.4,12170 v1(11800,12170)
I_PosB_2: R19_2.2 R20_2.2 U3.10 | length 514.3
  Top Layer w20: U3.10@12104.49,12170 v1(12370,12170)
  Bottom Layer w20: R19_2.2@12270,12017.4 12277.32,12017.4 12287.4,12027.48 R20_2.2@12287.4,12160 ; R20_2.2@12279.47,12160 12351.88,12160 12361.88,12170 v1(12370,12170)
I_PosB_3: R19_3.2 R20_3.2 U3.12 | length 348.1
  Top Layer w20: U3.12@12104.49,12270 v1(12230,12270)
  Bottom Layer w20: v1(12230,12270) R19_3.2@12332.6,12270 R20_3.2@12332.6,12390
IA1: R57_1.2 R73.1 U24_1.8 | length 72.3
  Bottom Layer w10: U24_1.8@2191.39,11820 2191.39,11840.5 2197,11846.11 R73.1@2197,11890
IA2: R57_2.2 R99.1 U24_2.8
IB1: R60_1.2 R74.1 U25_1.8 | length 76.5
  Bottom Layer w10: U25_1.8@2701.39,11820 2701.39,11840.5 2717,11856.11 R74.1@2717,11890
IB2: R60_2.2 R102.1 U25_2.8
IC1: R63_1.2 R75.1 U26_1.8 | length 92.5
  Bottom Layer w10: U26_1.8@3156.71,11820 3156.71,11838.5 3170,11851.79 R75.1@3170,11907
IC2: R63_2.2 R103.1 U26_2.8
IComp1: R93.1 U14_1.4 | length 268.6
  Top Layer w20: R93.1@2766.43,11246.91 2761.51,11246.91 2729.69,11278.72 2729.69,11369.11 U14_1.4@2820.42,11459.84
IComp2: R122.1 U14_2.4 | length 268.6
  Top Layer w20: R122.1@11467.92,12769.12 11463,12769.12 11431.18,12800.94 11431.18,12891.33 U14_2.4@11521.91,12982.06
nEnable1: U17.22 U18.4 | length 100.5
  Top Layer w10: U17.22@2429.88,10244.53 2429.88,10225.91 2442.42,10213.37 2456.98,10213.37 2457.38,10212.98 ; U18.4@2985.98,11287.98 2989.48,11287.98 U18.4@2992.42,11285.04
  Top Layer w20: v2(2992.42,11243.72) U18.4@2992.42,11285.04
nEnable2: U19.22 U20.4 | length 2179.5
  Top Layer w10: U19.22@9665.77,12895.39 9672.69,12895.39 9687.29,12910 v2(9690,12910)
  Top Layer w20: v2(11698.64,12738.72) U20.4@11698.64,12808.38
  Lay1 w10: v2(9690,12910) 10214.64,12910 10300.28,12824.36 11613,12824.36 v2(11698.64,12738.72)
NetC1_1: C1.1 C6.2 R1.1 R3.2 U1.3 U2.3 | length 1189.4
  Top Layer w20: U2.3@1597.09,12238.86 1597.78,12238.17 1660.93,12238.17 1671.72,12227.38 1757.68,12227.38 1759.16,12228.86 v1(1778.93,12228.86) R1.1@1855.2,12228.86 1857.95,12226.1 1857.95,12141.61 C1.1@1860.71,12138.86 ; R1.1@1855.2,12237.72 2037.48,12420 2340.98,12420 2390.94,12370.04 2422.44,12370.04 U1.3@2423.62,12368.86
  Bottom Layer w20: v1(1778.93,12228.86) R3.2@1855.2,12228.86 1857.95,12226.1 1857.95,12141.61 C6.2@1860.71,12138.86
NetC11_1: C11.1 C16.2 R7.1 R9.2 U3.3 U4.3 | length 1654.8
  Top Layer w20: v1(11260,12080) U4.3@11164.49,12080 11132.99,12080 11101.18,12048.19 11101.18,11927.28 11161.06,11867.4 R7.1@11220,11867.4 C11.1@11350,11867.4 ; v1(11740,12230) 11780,12270 U3.3@11915.51,12270
  Bottom Layer w20: R9.2@11347.16,11877.4 11345.86,11876.1 11218.46,11876.1 C16.2@11217.16,11874.8 11217.16,12037.16 v1(11260,12080) 11368.94,12188.94 11698.94,12188.94 v1(11740,12230)
NetC22_1_2: C22_1.2 L3_1.2 L4_1.1 R13_1.1 | length 5730.4
  Top Layer w50: C22_1.2@6188.66,10190 6188.66,10387.4 6381.89,10580.63 R13_1.1@6381.89,10620
  Top Layer w140: L3_1.2@3515.71,10177.54 6176.2,10177.54 C22_1.2@6188.66,10190 6188.66,9254.37 6628.74,8814.29 L4_1.1@6628.74,7830
NetC22_2_2: C22_2.2 L3_2.2 L4_2.1 R13_2.1 | length 5131.6
  Top Layer w50: v1(5570,10330) R13_2.1@5570,10461.89
  Top Layer w140: L3_2.2@3515.71,8934.39 4199.38,8934.39 4814.99,9550 C22_2.2@5658.66,9550 ; C22_2.2@5670,9550 5778.74,9441.26 L4_2.1@5778.74,7830
  Bottom Layer w50: v1@5570,10350 5570,9638.66 C22_2.2@5658.66,9550
NetC22_3_2: C22_3.2 L3_3.2 L4_3.1 R13_3.1 | length 4320.8
  Top Layer w50: v1(4520,10345.35) R13_3.1@4520,10461.89
  Top Layer w140: L3_3.2@3515.71,7677.93 4786.67,7677.93 L4_3.1@4938.74,7830 4968.66,7859.92 C22_3.2@4968.66,8910
  Bottom Layer w50: v1@4520,10350 4520,9358.66 C22_3.2@4968.66,8910
NetC27_1_2: C27_1.2 L5_1.2 L6_1.1 R15_1.1 | length 4149.9
  Top Layer w50: v1(9770,10350) R15_1.1@9770,10441.89
  Top Layer w140: C27_1.2@9881.34,8910 9881.26,8909.92 L6_1.1@9881.26,7830 10033.72,7677.54 L5_1.2@11310,7677.54
  Bottom Layer w50: v1(9770,10350) 9770,9021.34 C27_1.2@9881.34,8910
NetC27_2_2: C27_2.2 L5_2.2 L6_2.1 R15_2.1 | length 5191.3
  Top Layer w50: R15_2.1@8790,10451.89 8800,10441.89 v1(8800,10330)
  Top Layer w140: L6_2.1@9041.26,7840 9041.26,9279.92 C27_2.2@9301.34,9540 10310,9540 10916.46,8933.54 L5_2.2@11310,8933.54
  Bottom Layer w50: v1(8800,10330) 8800,10041.34 C27_2.2@9301.34,9540
NetC27_3_2: C27_3.2 L5_3.2 L6_3.1 R15_3.1 | length 6094.8
  Top Layer w50: R15_3.1@7910,10630 8141.34,10630 C27_3.2@8581.34,10190
  Top Layer w140: L6_3.1@8201.26,7840 8201.26,8971.26 8581.34,9351.34 C27_3.2@8581.34,10190 8593.8,10177.54 L5_3.2@11310,10177.54
NetC32_1: C32.1 R26.1 U7.2 | length 105.1
  Top Layer w20: R26.1@12295.55,13040.01 12295.73,13040.19 12400.33,13040.19 U7.2@12400.51,13040.36
NetC35_1: C35.1 L7.2 | length 134.4
  Top Layer w20: L7.2@12647.5,13324.21 12659.16,13312.56 12721.19,13312.56 12722.06,13311.69 C35.1@12776.68,13311.69
NetC36_1: C36.1 U9.7 | length 96.1
  Top Layer w20: C36.1@12880,13271.5 12886.89,13271.5 12894.39,13264 U9.7@12973,13264
NetC36_2: C36.2 L7.1 R31.2 U9.8 | length 348.1
  Top Layer w20: L7.1@12642.82,13196.03 12694,13196.03 12705.66,13207.69 12705.66,13208.28 12717.37,13220 12812.98,13220 12825.23,13207.75 R31.2@12830.15,13207.75 12830.53,13208.13 12879.62,13208.13 C36.2@12880,13208.5 12886.89,13208.5 12892.39,13214 U9.8@12973,13214
NetC37_2: C37.2 C42.2 R31.1 | length 221
  Top Layer w10: C37.2@12830.62,13311.69 12837.51,13311.69 12844.32,13318.5 12844.32,13328.38 12859.97,13344.03 12900.43,13344.03 12913.9,13357.5 12913.9,13393.55 12909.36,13398.08 C42.2@12909.36,13430.43
  Top Layer w20: R31.1@12830.15,13273.75 12830.39,13273.99 12830.39,13311.45 C37.2@12830.62,13311.69
NetC38_1: C38.1 R30.1 U8.2 | length 124.8
  Top Layer w20: C38.1@12070.82,13072.19 C38.1@12070.82,13065.3 ; U8.2@12074.89,13019.64 12071.65,13019.64 12070.82,13020.46 C38.1@12070.82,13065.3 ; R30.1@12115.91,13031.06 12117.72,13032.87 R30.1@12117.72,13037.79 12117.72,13042.71 12096.95,13063.49 12072.63,13063.49 C38.1@12070.82,13065.3
NetC42_1: C42.1 R33.1 R37.2 U9.5 | length 617.1
  Top Layer w20: v2(12560,13380) 12560.46,13379.54 R33.1@12595.6,13379.54 ; C42.1@12972.36,13430.43 12972.36,13364.5 12972.86,13364 U9.5@12973,13364
  Top Layer w25: C42.1@12972.36,13430.43 R37.2@12972.36,13497.64
  Bottom Layer w20: v2(12560,13380) 12650,13470 v2(12970,13470)
NetC46_1: C46.1 C47.2 L8.2 R34.1 R36.1 U9.2 | length 376.6
  Top Layer w20: U9.2@13167,13264 13293.79,13264 13296.01,13261.77 C47.2@13302.9,13261.77 13303.35,13262.22 C47.2@13307.75,13262.22 ; R34.1@13309.11,13361.79 13307.3,13359.98 13307.3,13262.67 C47.2@13307.75,13262.22 ; L8.2@13441.76,13262.67 13441.31,13262.22 C47.2@13307.75,13262.22
NetC48_2: C48.2 U9.6 | length 93.4
  Top Layer w20: C48.2@12880.2,13312.53 12881.17,13313.5 12972.5,13313.5 U9.6@12973,13314
NetC51_2: C51.2 R42.1 U11.4 U11.5 | length 122.2
  Top Layer w20: U11.4@12475.38,13416.91 U11.5@12437.98,13416.91 C51.2@12437.99,13460 12437.99,13458.82 12439.8,13457.01 12475.24,13457.01 R42.1@12477.05,13455.2
NetC56_1_1: C56_1.1 R57_1.1 R58_1.2 | length 162.2
  Top Layer w10: C56_1.1@2522.51,11758.99 2593.18,11758.99 2625.51,11791.32 R57_1.1@2625.51,11796.24
  Top Layer w20: R57_1.1@2625.51,11796.24 R58_1.2@2666.4,11796.24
